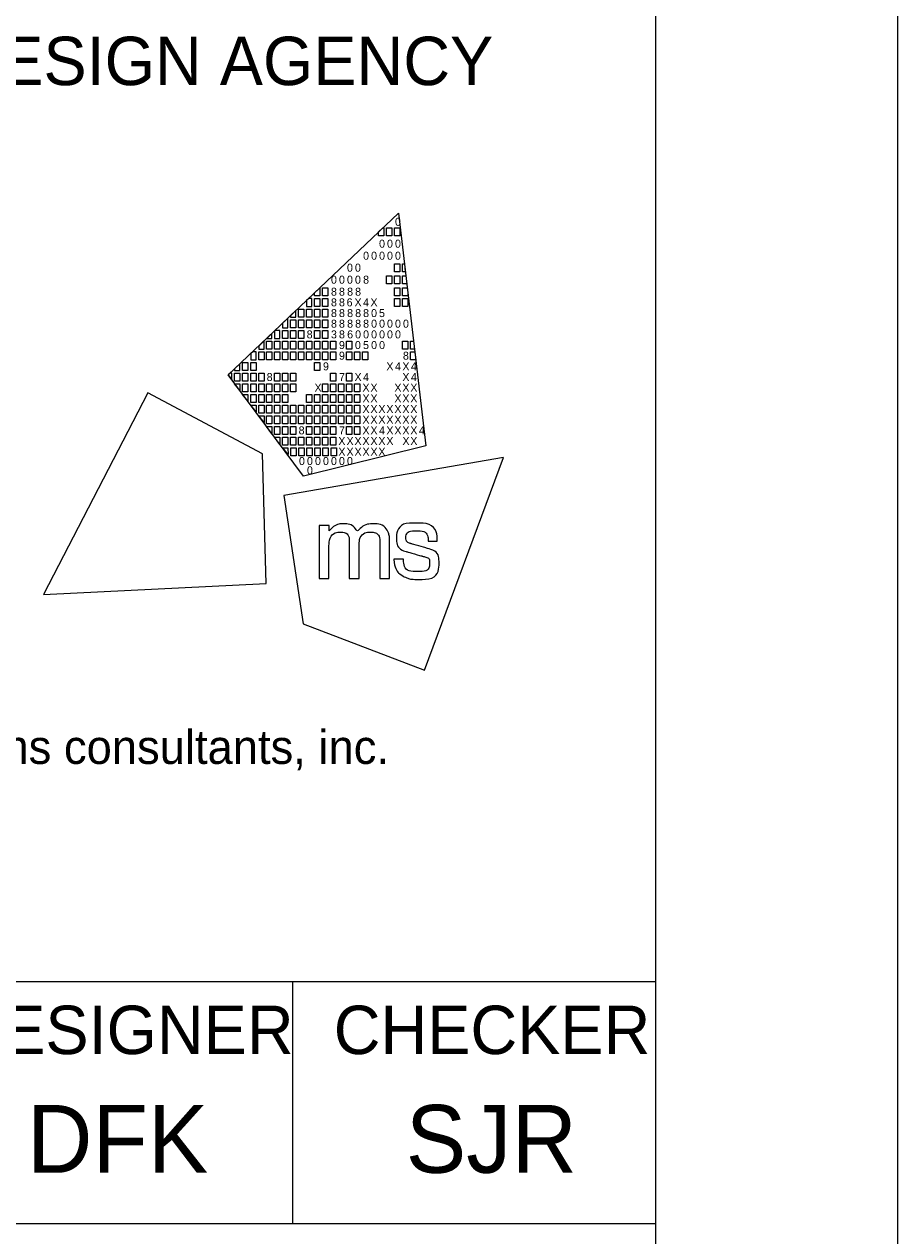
# Model space of a CAD drawing. Extents: x 0 to 34, y 0 to 22.
# Drawn here: x 32.196 to 34, y 2.475 to 4.976 of the extents above; entities that cross this region are included whole.
import ezdxf

# ---------------------------------------------------------------- set-up
doc = ezdxf.new("R2010")
doc.units = 0
for name, color, linetype in [('SH_Border', 7, 'Continuous'), ('SH_Cut_Line', 7, 'Continuous'), ('SH_Data', 7, 'Continuous'), ('SH_Text', 7, 'Continuous')]:
    doc.layers.add(name, color=color, linetype=linetype)

msp = doc.modelspace()

# ---------------------------------------------------------------- linework, layer by layer
at = {"layer": 'SH_Border'}
for p, q in [((32, 3), (33.5, 3)), ((32.75, 3), (32.75, 2.5)), ((32, 2.5), (33.5, 2.5))]:
    msp.add_line(p, q, dxfattribs=at)
msp.add_lwpolyline([(1.5, 21.5), (33.5, 21.5), (33.5, 0.5), (1.5, 0.5)], close=True, dxfattribs=at)
at = {"layer": 'SH_Cut_Line'}
msp.add_lwpolyline([(0, 0), (34, 0), (34, 22), (0, 22)], close=True, dxfattribs=at)
at = {"layer": 'SH_Data'}
msp.add_line((32.75, 4), (32.75, 4), dxfattribs=at)
at = {"layer": 'SH_Text'}
for p, q in [((32.6175, 4.2519), (32.9688, 4.5861)), ((32.9688, 4.5861), (32.9688, 4.5861)), ((32.9688, 4.5861), (33.0253, 4.1052)), ((32.773, 4.043), (32.6175, 4.2519)), ((33.0253, 4.1052), (32.773, 4.043))]:
    msp.add_line(p, q, dxfattribs=at)
for points in [[(32.9279, 4.5472), (32.9369, 4.5558), (32.9389, 4.5558), (32.9389, 4.5393), (32.9279, 4.5393)], [(32.9444, 4.5558), (32.9554, 4.5558), (32.9554, 4.5393), (32.9444, 4.5393)], [(32.9609, 4.5558), (32.9719, 4.5558), (32.9719, 4.5393), (32.9609, 4.5393)], [(32.9606, 4.4815), (32.9716, 4.4815), (32.9716, 4.465), (32.9606, 4.465)], [(32.9771, 4.4815), (32.9811, 4.4815), (32.983, 4.465), (32.9771, 4.465)], [(32.9441, 4.4567), (32.9551, 4.4567), (32.9551, 4.4402), (32.9441, 4.4402)], [(32.9606, 4.4567), (32.9716, 4.4567), (32.9716, 4.4402), (32.9606, 4.4402)], [(32.9771, 4.4567), (32.984, 4.4567), (32.9859, 4.4402), (32.9771, 4.4402)], [(32.7953, 4.4211), (32.8064, 4.4316), (32.8064, 4.4154), (32.7953, 4.4154)], [(32.8123, 4.4319), (32.8233, 4.4319), (32.8233, 4.4154), (32.8123, 4.4154)], [(32.9606, 4.4319), (32.9716, 4.4319), (32.9716, 4.4154), (32.9606, 4.4154)], [(32.9771, 4.4319), (32.9869, 4.4319), (32.9881, 4.4218), (32.9881, 4.4154), (32.9771, 4.4154)], [(32.7958, 4.4099), (32.8068, 4.4099), (32.8068, 4.3934), (32.7958, 4.3934)], [(32.8123, 4.4099), (32.8233, 4.4099), (32.8233, 4.3934), (32.8123, 4.3934)], [(32.9606, 4.4099), (32.9716, 4.4099), (32.9716, 4.3934), (32.9606, 4.3934)], [(32.9771, 4.4099), (32.9881, 4.4099), (32.9881, 4.3934), (32.9771, 4.3934)], [(32.7627, 4.3879), (32.7737, 4.3879), (32.7737, 4.3714), (32.7627, 4.3714)], [(32.7793, 4.3879), (32.7903, 4.3879), (32.7903, 4.3714), (32.7793, 4.3714)], [(32.7958, 4.3879), (32.8068, 4.3879), (32.8068, 4.3714), (32.7958, 4.3714)], [(32.8123, 4.3879), (32.8233, 4.3879), (32.8233, 4.3714), (32.8123, 4.3714)], [(32.7462, 4.3659), (32.7572, 4.3659), (32.7572, 4.3494), (32.7462, 4.3494)], [(32.7627, 4.3659), (32.7737, 4.3659), (32.7737, 4.3494), (32.7627, 4.3494)], [(32.7793, 4.3659), (32.7903, 4.3659), (32.7903, 4.3494), (32.7793, 4.3494)], [(32.7958, 4.3659), (32.8068, 4.3659), (32.8068, 4.3494), (32.7958, 4.3494)], [(32.8123, 4.3659), (32.8233, 4.3659), (32.8233, 4.3494), (32.8123, 4.3494)], [(32.7297, 4.3439), (32.7407, 4.3439), (32.7407, 4.3273), (32.7297, 4.3273)], [(32.7462, 4.3439), (32.7572, 4.3439), (32.7572, 4.3273), (32.7462, 4.3273)], [(32.7627, 4.3439), (32.7737, 4.3439), (32.7737, 4.3273), (32.7627, 4.3273)], [(32.7958, 4.3439), (32.8068, 4.3439), (32.8068, 4.3273), (32.7958, 4.3273)], [(32.8123, 4.3439), (32.8233, 4.3439), (32.8233, 4.3273), (32.8123, 4.3273)], [(32.6967, 4.3218), (32.7077, 4.3218), (32.7077, 4.3053), (32.6967, 4.3053)], [(32.7132, 4.3218), (32.7242, 4.3218), (32.7242, 4.3053), (32.7132, 4.3053)], [(32.7297, 4.3218), (32.7407, 4.3218), (32.7407, 4.3053), (32.7297, 4.3053)], [(32.7462, 4.3218), (32.7572, 4.3218), (32.7572, 4.3053), (32.7462, 4.3053)], [(32.7627, 4.3218), (32.7737, 4.3218), (32.7737, 4.3053), (32.7627, 4.3053)], [(32.7793, 4.3218), (32.7903, 4.3218), (32.7903, 4.3053), (32.7793, 4.3053)], [(32.7958, 4.3218), (32.8068, 4.3218), (32.8068, 4.3053), (32.7958, 4.3053)], [(32.8123, 4.3218), (32.8233, 4.3218), (32.8233, 4.3053), (32.8123, 4.3053)], [(32.8288, 4.3218), (32.8398, 4.3218), (32.8398, 4.3053), (32.8288, 4.3053)], [(32.8618, 4.3218), (32.8728, 4.3218), (32.8728, 4.3053), (32.8618, 4.3053)], [(32.9771, 4.3218), (32.9881, 4.3218), (32.9881, 4.3053), (32.9771, 4.3053)], [(32.9935, 4.3218), (32.9998, 4.3218), (33.0018, 4.3053), (32.9935, 4.3053)], [(32.6471, 4.2778), (32.6581, 4.2778), (32.6581, 4.2613), (32.6471, 4.2613)], [(32.6637, 4.2778), (32.6747, 4.2778), (32.6747, 4.2613), (32.6637, 4.2613)], [(32.6802, 4.2998), (32.6912, 4.2998), (32.6912, 4.2833), (32.6802, 4.2833)], [(32.6967, 4.2998), (32.7077, 4.2998), (32.7077, 4.2833), (32.6967, 4.2833)], [(32.7132, 4.2998), (32.7242, 4.2998), (32.7242, 4.2833), (32.7132, 4.2833)], [(32.7297, 4.2998), (32.7407, 4.2998), (32.7407, 4.2833), (32.7297, 4.2833)], [(32.7462, 4.2998), (32.7572, 4.2998), (32.7572, 4.2833), (32.7462, 4.2833)], [(32.7627, 4.2998), (32.7737, 4.2998), (32.7737, 4.2833), (32.7627, 4.2833)], [(32.7793, 4.2998), (32.7903, 4.2998), (32.7903, 4.2833), (32.7793, 4.2833)], [(32.7958, 4.2998), (32.8068, 4.2998), (32.8068, 4.2833), (32.7958, 4.2833)], [(32.7958, 4.2778), (32.8068, 4.2778), (32.8068, 4.2613), (32.7958, 4.2613)], [(32.8123, 4.2998), (32.8233, 4.2998), (32.8233, 4.2833), (32.8123, 4.2833)], [(32.8288, 4.2998), (32.8398, 4.2998), (32.8398, 4.2833), (32.8288, 4.2833)], [(32.8618, 4.2998), (32.8728, 4.2998), (32.8728, 4.2833), (32.8618, 4.2833)], [(32.8783, 4.2998), (32.8893, 4.2998), (32.8893, 4.2833), (32.8783, 4.2833)], [(32.8947, 4.2998), (32.9057, 4.2998), (32.9057, 4.2833), (32.8947, 4.2833)], [(32.9935, 4.2998), (33.0024, 4.2998), (33.0044, 4.2833), (32.9935, 4.2833)], [(32.6306, 4.2558), (32.6416, 4.2558), (32.6416, 4.2393), (32.6306, 4.2393)], [(32.6471, 4.2558), (32.6581, 4.2558), (32.6581, 4.2393), (32.6471, 4.2393)], [(32.6637, 4.2558), (32.6747, 4.2558), (32.6747, 4.2393), (32.6637, 4.2393)], [(32.6802, 4.2558), (32.6912, 4.2558), (32.6912, 4.2393), (32.6802, 4.2393)], [(32.7132, 4.2558), (32.7242, 4.2558), (32.7242, 4.2393), (32.7132, 4.2393)], [(32.7297, 4.2558), (32.7407, 4.2558), (32.7407, 4.2393), (32.7297, 4.2393)], [(32.7462, 4.2558), (32.7572, 4.2558), (32.7572, 4.2393), (32.7462, 4.2393)], [(32.8288, 4.2558), (32.8398, 4.2558), (32.8398, 4.2393), (32.8288, 4.2393)], [(32.8618, 4.2558), (32.8728, 4.2558), (32.8728, 4.2393), (32.8618, 4.2393)], [(32.6306, 4.2338), (32.6416, 4.2338), (32.6416, 4.22)], [(32.6471, 4.2338), (32.6581, 4.2338), (32.6581, 4.2173), (32.6471, 4.2173)], [(32.6637, 4.2338), (32.6747, 4.2338), (32.6747, 4.2173), (32.6637, 4.2173)], [(32.6802, 4.2338), (32.6912, 4.2338), (32.6912, 4.2173), (32.6802, 4.2173)], [(32.6967, 4.2338), (32.7077, 4.2338), (32.7077, 4.2173), (32.6967, 4.2173)], [(32.7132, 4.2338), (32.7242, 4.2338), (32.7242, 4.2173), (32.7132, 4.2173)], [(32.7297, 4.2338), (32.7407, 4.2338), (32.7407, 4.2173), (32.7297, 4.2173)], [(32.7462, 4.2338), (32.7572, 4.2338), (32.7572, 4.2173), (32.7462, 4.2173)], [(32.8123, 4.2338), (32.8233, 4.2338), (32.8233, 4.2173), (32.8123, 4.2173)], [(32.8288, 4.2338), (32.8398, 4.2338), (32.8398, 4.2173), (32.8288, 4.2173)], [(32.8453, 4.2338), (32.8563, 4.2338), (32.8563, 4.2173), (32.8453, 4.2173)], [(32.8618, 4.2338), (32.8728, 4.2338), (32.8728, 4.2173), (32.8618, 4.2173)], [(32.8783, 4.2338), (32.8893, 4.2338), (32.8893, 4.2173), (32.8783, 4.2173)], [(32.6471, 4.2117), (32.6581, 4.2117), (32.6581, 4.198)], [(32.6637, 4.2117), (32.6747, 4.2117), (32.6747, 4.1952), (32.6637, 4.1952)], [(32.6802, 4.2117), (32.6912, 4.2117), (32.6912, 4.1952), (32.6802, 4.1952)], [(32.6967, 4.2117), (32.7077, 4.2117), (32.7077, 4.1952), (32.6967, 4.1952)], [(32.7132, 4.2117), (32.7242, 4.2117), (32.7242, 4.1952), (32.7132, 4.1952)], [(32.7297, 4.2117), (32.7407, 4.2117), (32.7407, 4.1952), (32.7297, 4.1952)], [(32.7793, 4.2117), (32.7903, 4.2117), (32.7903, 4.1952), (32.7793, 4.1952)], [(32.7958, 4.2117), (32.8068, 4.2117), (32.8068, 4.1952), (32.7958, 4.1952)], [(32.8123, 4.2117), (32.8233, 4.2117), (32.8233, 4.1952), (32.8123, 4.1952)], [(32.8288, 4.2117), (32.8398, 4.2117), (32.8398, 4.1952), (32.8288, 4.1952)], [(32.8453, 4.2117), (32.8563, 4.2117), (32.8563, 4.1952), (32.8453, 4.1952)], [(32.8618, 4.2117), (32.8728, 4.2117), (32.8728, 4.1952), (32.8618, 4.1952)], [(32.8783, 4.2117), (32.8893, 4.2117), (32.8893, 4.1952), (32.8783, 4.1952)], [(32.6637, 4.1897), (32.6747, 4.1897), (32.6747, 4.176)], [(32.6747, 4.1897), (32.6747, 4.1897), (32.6747, 4.1897)], [(32.6802, 4.1897), (32.6912, 4.1897), (32.6912, 4.1732), (32.6802, 4.1732)], [(32.6967, 4.1897), (32.7077, 4.1897), (32.7077, 4.1732), (32.6967, 4.1732)], [(32.7132, 4.1897), (32.7242, 4.1897), (32.7242, 4.1732), (32.7132, 4.1732)], [(32.7297, 4.1897), (32.7407, 4.1897), (32.7407, 4.1732), (32.7297, 4.1732)], [(32.7462, 4.1897), (32.7572, 4.1897), (32.7572, 4.1732), (32.7462, 4.1732)], [(32.7627, 4.1897), (32.7737, 4.1897), (32.7737, 4.1732), (32.7627, 4.1732)], [(32.7793, 4.1897), (32.7903, 4.1897), (32.7903, 4.1732), (32.7793, 4.1732)], [(32.7958, 4.1897), (32.8068, 4.1897), (32.8068, 4.1732), (32.7958, 4.1732)], [(32.8123, 4.1897), (32.8233, 4.1897), (32.8233, 4.1732), (32.8123, 4.1732)], [(32.8288, 4.1897), (32.8398, 4.1897), (32.8398, 4.1732), (32.8288, 4.1732)], [(32.8453, 4.1897), (32.8563, 4.1897), (32.8563, 4.1732), (32.8453, 4.1732)], [(32.8618, 4.1897), (32.8728, 4.1897), (32.8728, 4.1732), (32.8618, 4.1732)], [(32.8783, 4.1897), (32.8893, 4.1897), (32.8893, 4.1732), (32.8783, 4.1732)], [(32.6802, 4.1677), (32.6912, 4.1677), (32.6912, 4.154)], [(32.6967, 4.1677), (32.7077, 4.1677), (32.7077, 4.1512), (32.6967, 4.1512)], [(32.7132, 4.1677), (32.7242, 4.1677), (32.7242, 4.1512), (32.7132, 4.1512)], [(32.7297, 4.1677), (32.7407, 4.1677), (32.7407, 4.1512), (32.7297, 4.1512)], [(32.7462, 4.1677), (32.7572, 4.1677), (32.7572, 4.1512), (32.7462, 4.1512)], [(32.7627, 4.1677), (32.7737, 4.1677), (32.7737, 4.1512), (32.7627, 4.1512)], [(32.7793, 4.1677), (32.7903, 4.1677), (32.7903, 4.1512), (32.7793, 4.1512)], [(32.7958, 4.1677), (32.8068, 4.1677), (32.8068, 4.1512), (32.7958, 4.1512)], [(32.8123, 4.1677), (32.8233, 4.1677), (32.8233, 4.1512), (32.8123, 4.1512)], [(32.8288, 4.1677), (32.8398, 4.1677), (32.8398, 4.1512), (32.8288, 4.1512)], [(32.8453, 4.1677), (32.8563, 4.1677), (32.8563, 4.1512), (32.8453, 4.1512)], [(32.8618, 4.1677), (32.8728, 4.1677), (32.8728, 4.1512), (32.8618, 4.1512)], [(32.8783, 4.1677), (32.8893, 4.1677), (32.8893, 4.1512), (32.8783, 4.1512)], [(32.7077, 4.1305), (32.6965, 4.1457), (32.7077, 4.1457)], [(32.7132, 4.1457), (32.7242, 4.1457), (32.7242, 4.1292), (32.7132, 4.1292)], [(32.7297, 4.1457), (32.7407, 4.1457), (32.7407, 4.1292), (32.7297, 4.1292)], [(32.7462, 4.1457), (32.7572, 4.1457), (32.7572, 4.1292), (32.7462, 4.1292)], [(32.7793, 4.1457), (32.7903, 4.1457), (32.7903, 4.1292), (32.7793, 4.1292)], [(32.7958, 4.1457), (32.8068, 4.1457), (32.8068, 4.1292), (32.7958, 4.1292)], [(32.8123, 4.1457), (32.8233, 4.1457), (32.8233, 4.1292), (32.8123, 4.1292)], [(32.8288, 4.1457), (32.8398, 4.1457), (32.8398, 4.1292), (32.8288, 4.1292)], [(32.8618, 4.1457), (32.8728, 4.1457), (32.8728, 4.1292), (32.8618, 4.1292)], [(32.8783, 4.1457), (32.8893, 4.1457), (32.8893, 4.1292), (32.8783, 4.1292)], [(32.724, 4.1082), (32.7132, 4.1237), (32.7242, 4.1237)], [(32.7297, 4.1237), (32.7407, 4.1237), (32.7407, 4.1072), (32.7297, 4.1072)], [(32.7302, 4.1017), (32.7407, 4.1017), (32.7408, 4.0875)], [(32.7462, 4.1237), (32.7572, 4.1237), (32.7572, 4.1072), (32.7462, 4.1072)], [(32.7463, 4.1017), (32.7573, 4.1017), (32.7573, 4.0852), (32.7463, 4.0852)], [(32.7627, 4.1237), (32.7737, 4.1237), (32.7737, 4.1072), (32.7627, 4.1072)], [(32.763, 4.1017), (32.774, 4.1017), (32.774, 4.0852), (32.763, 4.0852)], [(32.7793, 4.1237), (32.7903, 4.1237), (32.7903, 4.1072), (32.7793, 4.1072)], [(32.7794, 4.1017), (32.7904, 4.1017), (32.7904, 4.0852), (32.7794, 4.0852)], [(32.7958, 4.1237), (32.8068, 4.1237), (32.8068, 4.1072), (32.7958, 4.1072)], [(32.796, 4.1017), (32.807, 4.1017), (32.807, 4.0852), (32.796, 4.0852)], [(32.8123, 4.1237), (32.8233, 4.1237), (32.8233, 4.1072), (32.8123, 4.1072)], [(32.8129, 4.1017), (32.8239, 4.1017), (32.8239, 4.0851), (32.8129, 4.0851)], [(32.8288, 4.1237), (32.8398, 4.1237), (32.8398, 4.1072), (32.8288, 4.1072)], [(32.8296, 4.1017), (32.8406, 4.1017), (32.8406, 4.0851), (32.8296, 4.0851)]]:
    msp.add_lwpolyline(points, close=True, dxfattribs=at)
for points in [[(32.7903, 4.4099), (32.7836, 4.4099), (32.7793, 4.4058), (32.7793, 4.3934), (32.7903, 4.3934), (32.7903, 4.4099)], [(32.7572, 4.3849), (32.7462, 4.3744), (32.7462, 4.3714), (32.7572, 4.3714), (32.7572, 4.3849)], [(32.7407, 4.3691), (32.7297, 4.3587), (32.7297, 4.3494), (32.7407, 4.3494), (32.7407, 4.3691)], [(32.7077, 4.3377), (32.6968, 4.3273), (32.7077, 4.3273), (32.7077, 4.3377)], [(32.7242, 4.3439), (32.7141, 4.3439), (32.7132, 4.343), (32.7132, 4.3273), (32.7242, 4.3273), (32.7242, 4.3439)], [(32.6912, 4.322), (32.6802, 4.3115), (32.6802, 4.3053), (32.6912, 4.3053), (32.6912, 4.322)], [(32.6747, 4.2998), (32.6679, 4.2998), (32.6637, 4.2958), (32.6637, 4.2833), (32.6747, 4.2833), (32.6747, 4.2998)], [(32.6251, 4.2558), (32.6216, 4.2558), (32.6175, 4.2519), (32.6251, 4.2417), (32.6251, 4.2558)], [(32.6416, 4.2749), (32.6306, 4.2644), (32.6306, 4.2613), (32.6416, 4.2613), (32.6416, 4.2749)], [(32.4512, 4.2149), (32.2359, 3.7988), (32.6956, 3.8215), (32.6884, 4.0892), (32.4512, 4.2149)], [(33.0229, 3.6422), (33.1859, 4.0814), (32.7324, 4.0029), (32.7722, 3.7381), (33.0229, 3.6422)]]:
    msp.add_lwpolyline(points, dxfattribs=at)
for points in [[(32.8048, 3.8315), (32.8048, 3.8315), (32.8048, 3.9409), (32.8048, 3.9409), (32.8048, 3.9409), (32.8255, 3.9409), (32.8255, 3.9409), (32.8255, 3.9409), (32.8255, 3.9297), (32.8255, 3.9297), (32.8346, 3.9399), (32.8457, 3.9445), (32.8555, 3.9445), (32.8688, 3.9445), (32.8791, 3.9372), (32.8837, 3.9266), (32.8915, 3.9381), (32.905, 3.9446), (32.9166, 3.9446), (32.9325, 3.9446), (32.9451, 3.935), (32.9494, 3.9213), (32.9494, 3.9212), (32.9494, 3.9212), (32.9494, 3.9212), (32.9501, 3.919), (32.9506, 3.9172), (32.9506, 3.9071), (32.9506, 3.9071), (32.9506, 3.8314), (32.9506, 3.8314), (32.9506, 3.8314), (32.9303, 3.8314), (32.9303, 3.8314), (32.9303, 3.8314), (32.9303, 3.9048), (32.9303, 3.9048), (32.9303, 3.9201), (32.9219, 3.9274), (32.911, 3.9274), (32.8995, 3.9274), (32.8879, 3.9171), (32.8879, 3.9001), (32.8879, 3.9001), (32.8879, 3.8315), (32.8879, 3.8315), (32.8879, 3.8315), (32.8674, 3.8315), (32.8674, 3.8315), (32.8674, 3.8315), (32.8674, 3.9059), (32.8674, 3.9059), (32.8674, 3.9203), (32.8588, 3.9274), (32.8496, 3.9274), (32.8384, 3.9274), (32.8254, 3.917), (32.8254, 3.8962), (32.8254, 3.8962), (32.8254, 3.8315), (32.8254, 3.8315), (32.8254, 3.8315), (32.8048, 3.8315), (32.8048, 3.8315)], [(32.9595, 3.8709), (32.9595, 3.8709), (32.9595, 3.8717), (32.9595, 3.8717), (32.9595, 3.8717), (32.9603, 3.8717), (32.9603, 3.8717), (32.9603, 3.8717), (32.9783, 3.8717), (32.9783, 3.8717), (32.9783, 3.8717), (32.9789, 3.8717), (32.9789, 3.8717), (32.9789, 3.8717), (32.979, 3.871), (32.979, 3.871), (32.9803, 3.8554), (32.9887, 3.846), (33.009, 3.846), (33.0273, 3.846), (33.0333, 3.8554), (33.0333, 3.8631), (33.0333, 3.8732), (33.0256, 3.8758), (33.0175, 3.878), (33.0175, 3.878), (32.987, 3.8867), (32.987, 3.8867), (32.972, 3.8909), (32.9648, 3.9019), (32.9648, 3.9142), (32.9648, 3.9303), (32.9768, 3.9462), (33.0052, 3.9462), (33.0348, 3.9462), (33.0489, 3.9285), (33.0489, 3.9095), (33.0489, 3.9095), (33.0489, 3.9087), (33.0489, 3.9087), (33.0489, 3.9087), (33.0482, 3.9087), (33.0482, 3.9087), (33.0482, 3.9087), (33.0312, 3.9087), (33.0312, 3.9087), (33.0312, 3.9087), (33.0305, 3.9087), (33.0305, 3.9087), (33.0305, 3.9087), (33.0305, 3.9094), (33.0305, 3.9094), (33.0301, 3.9208), (33.0226, 3.93), (33.0056, 3.93), (32.9891, 3.93), (32.9843, 3.9218), (32.9843, 3.9157), (32.9843, 3.9108), (32.9869, 3.9059), (32.9959, 3.9033), (32.9959, 3.9033), (33.0255, 3.8948), (33.0255, 3.8948), (33.0462, 3.8889), (33.0527, 3.8777), (33.0527, 3.8639), (33.0527, 3.8462), (33.041, 3.8298), (33.0087, 3.8298), (32.9952, 3.8298), (32.9877, 3.8321), (32.9823, 3.8348), (32.969, 3.8414), (32.9609, 3.8536), (32.9595, 3.8709)]]:
    msp.add_open_spline(points, degree=3, dxfattribs=at)

# ---------------------------------------------------------------- texts
at = {"layer": 'SH_Border'}
msp.add_text('ms consultants, inc.', height=0.07, rotation=360, dxfattribs=at).set_placement((32.1273, 3.4489))
at = {"layer": 'SH_Data'}
for s, height, p in [('DESIGN AGENCY', 0.1, (32.05, 4.85)), ('DESIGNER', 0.1, (32.054, 2.85)), ('CHECKER', 0.1, (32.8352, 2.85)), ('DFK', 0.14, (32.2017, 2.605)), ('SJR', 0.14, (32.9839, 2.605))]:
    msp.add_text(s, height=height, dxfattribs=at).set_placement(p)
at = {"layer": 'SH_Text'}
for s, p in [('0', (32.9617, 4.5597)), ('0', (32.9288, 4.5145)), ('0', (32.9452, 4.5145)), ('0', (32.9617, 4.5145)), ('0', (32.8958, 4.4897)), ('0', (32.9123, 4.4897)), ('0', (32.9288, 4.4897)), ('0', (32.9452, 4.4897)), ('0', (32.9617, 4.4897)), ('0', (32.8625, 4.465)), ('0', (32.879, 4.465)), ('0', (32.8295, 4.4402)), ('0', (32.846, 4.4402)), ('0', (32.8625, 4.4402)), ('0', (32.879, 4.4402)), ('8', (32.8958, 4.4402)), ('8', (32.8295, 4.4154)), ('8', (32.846, 4.4154)), ('8', (32.8628, 4.4154)), ('8', (32.8793, 4.4154)), ('8', (32.8295, 4.3934)), ('8', (32.846, 4.3934)), ('6', (32.8618, 4.3934)), ('X', (32.8781, 4.3934)), ('4', (32.8958, 4.3934)), ('X', (32.911, 4.3934)), ('8', (32.8295, 4.3713)), ('8', (32.846, 4.3713)), ('8', (32.8628, 4.3713)), ('8', (32.8794, 4.3713)), ('8', (32.8958, 4.3713)), ('0', (32.9123, 4.3713)), ('5', (32.9287, 4.3713)), ('8', (32.8295, 4.3494)), ('8', (32.846, 4.3494)), ('8', (32.8628, 4.3494)), ('8', (32.8794, 4.3494)), ('8', (32.8958, 4.3494)), ('0', (32.9123, 4.3494)), ('0', (32.9288, 4.3494)), ('0', (32.9452, 4.3494)), ('0', (32.9617, 4.3494)), ('0', (32.9782, 4.3494)), ('8', (32.7793, 4.3273)), ('3', (32.8295, 4.3273)), ('8', (32.846, 4.3273)), ('6', (32.8629, 4.3273)), ('0', (32.8793, 4.3273)), ('0', (32.8958, 4.3273)), ('0', (32.9123, 4.3273)), ('0', (32.9288, 4.3273)), ('0', (32.9452, 4.3273)), ('0', (32.9617, 4.3273)), ('9', (32.846, 4.3053)), ('0', (32.879, 4.3053)), ('5', (32.8957, 4.3053)), ('0', (32.9123, 4.3053)), ('0', (32.9288, 4.3053)), ('9', (32.813, 4.2613)), ('9', (32.846, 4.2833)), ('X', (32.9439, 4.2613)), ('4', (32.9617, 4.2613)), ('X', (32.9769, 4.2613)), ('8', (32.9781, 4.2833)), ('4', (32.9946, 4.2613)), ('8', (32.6967, 4.2393)), ('7', (32.846, 4.2393)), ('X', (32.8781, 4.2393)), ('4', (32.8958, 4.2393)), ('X', (32.9769, 4.2393)), ('4', (32.9946, 4.2393)), ('X', (32.7955, 4.2173)), ('X', (32.8945, 4.2173)), ('X', (32.911, 4.2173)), ('X', (32.9604, 4.2173)), ('X', (32.9769, 4.2173)), ('X', (32.9933, 4.2173)), ('X', (32.8945, 4.1952)), ('X', (32.911, 4.1952)), ('X', (32.9604, 4.1952)), ('X', (32.9769, 4.1952)), ('X', (32.9933, 4.1952)), ('X', (32.8945, 4.1732)), ('X', (32.911, 4.1732)), ('X', (32.9274, 4.1732)), ('X', (32.9439, 4.1732)), ('X', (32.9604, 4.1732)), ('X', (32.9769, 4.1732)), ('X', (32.9933, 4.1732)), ('X', (32.8945, 4.1512)), ('X', (32.911, 4.1512)), ('X', (32.9274, 4.1512)), ('X', (32.9439, 4.1512)), ('X', (32.9604, 4.1512)), ('X', (32.9769, 4.1512)), ('X', (32.9933, 4.1512)), ('8', (32.7627, 4.1292)), ('7', (32.846, 4.1292)), ('X', (32.8945, 4.1292)), ('X', (32.911, 4.1292)), ('4', (32.9288, 4.1292)), ('X', (32.9439, 4.1292)), ('X', (32.9604, 4.1292)), ('X', (32.9769, 4.1292)), ('X', (32.9933, 4.1292)), ('4', (33.0111, 4.1292)), ('X', (32.8447, 4.1072)), ('X', (32.8447, 4.0851)), ('X', (32.8616, 4.1072)), ('X', (32.8616, 4.0851)), ('X', (32.878, 4.1072)), ('X', (32.878, 4.0851)), ('X', (32.8945, 4.1072)), ('X', (32.8945, 4.0851)), ('X', (32.911, 4.1072)), ('X', (32.911, 4.0851)), ('X', (32.9274, 4.1072)), ('X', (32.9274, 4.0851)), ('X', (32.9439, 4.1072)), ('X', (32.9771, 4.1072)), ('X', (32.9933, 4.1072)), ('0', (32.7634, 4.0659)), ('0', (32.7799, 4.0659)), ('0', (32.7965, 4.0659)), ('0', (32.813, 4.0659)), ('0', (32.8295, 4.0659)), ('0', (32.846, 4.0659)), ('0', (32.8625, 4.0659)), ('0', (32.7799, 4.0467))]:
    msp.add_text(s, height=0.0165, rotation=360, dxfattribs=at).set_placement(p)

doc.saveas('drawing.dxf')
